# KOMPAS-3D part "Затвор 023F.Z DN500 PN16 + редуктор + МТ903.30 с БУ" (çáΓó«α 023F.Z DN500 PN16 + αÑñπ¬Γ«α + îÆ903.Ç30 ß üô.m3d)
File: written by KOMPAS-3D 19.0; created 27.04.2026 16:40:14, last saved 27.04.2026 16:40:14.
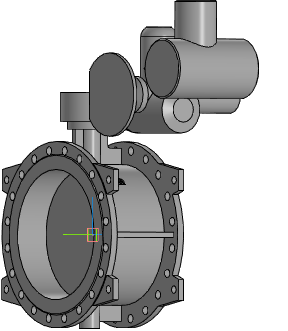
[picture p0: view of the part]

Document properties: Полное имя файла: ..\..\Затвор 023F.Z DN400-DN1600 + редуктор + МТ903\Затвор 023F.Z DN500 PN16 + редуктор + МТ903.А30 с БУ.a3d

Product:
- Part/product: Затвор 023F.Z DN500 PN16 + редуктор + МТ903.30 с БУ
    Масса: 606.537

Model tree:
1. Операция без истории:1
